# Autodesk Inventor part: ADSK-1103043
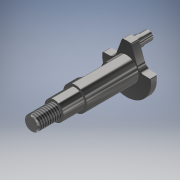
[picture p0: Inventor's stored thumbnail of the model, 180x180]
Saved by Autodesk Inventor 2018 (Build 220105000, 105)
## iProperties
Shininess: 50.0
Length Units: 11272
Angle Units: 11279
Time Units: 11290
Mass Units: 11286
Length Display Precision: 4
Angle Display Precision: 2
Compacted: True
Created: 2000-11
Part Number: ADSK-1103043
Document SubType Name: Modeling
Description: CRANKSHAFT
Mass: 18.2834 g
Surface Area: 21.3592 cm^2
Volume: 2.33206 cm^3
Density: 7.84 g/cm^3
Material: Steel, High Strength Low Alloy
Appearance: Steel - Polished
Density: 0.0
Volumn: 0.0
Area: 0.0
PropertySet Name: Model Information
Control State: 0
Master: False
Checked Out: False
Author: Autodesk, Inc.
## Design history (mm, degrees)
node "Extrusion1" dims "d1" = 30.2625, "d2" = 0
  sketch "Sketch2"
    geometry: C1 r 4.001 at (0, 0); 1 further point
    constraints: 1 centre point, 1 coincident
    dimensions: "d0" = 8.001 diameter of C1
node "Extrusion2" dims "d4" = 3.175, "d5" = 0
  sketch "Sketch3"
    geometry: C1 r 4.001 at (0, 0) reference; C2 r 10.224 at (0, 0)
    constraints: 1 centre point, 1 coincident
    dimensions: "d3" = 20.447 diameter of C2
node "Extrusion6" dims "d23" = 21.5, "d24" = 0
  sketch "Sketch7"
    geometry: C1 r 4.001 at (0, 0) reference; C2 r 5.001 at (0, 0)
    constraints: 1 centre point, 1 coincident
    dimensions: "d22" = 10.00125 diameter of C2
node "Extrusion3" dims "d9" = 3.175, "d10" = 0
  sketch "Sketch4"
    geometry: L1 (-10.144, 1.27)-(-5.15, 1.27); L2 (-5.15, 1.27)-(-1.905, 10.044); L3 (1.905, 10.044)-(5.15, 1.27); L4 (5.15, 1.27)-(10.144, 1.27); C1 r 4.001 at (0, 0) reference; A1 r 10.224 centre (0, 0) between (-10.144, 1.27) and (-1.905, 10.044) reference
    constraints: 8 end point, 4 point on circle, 2 collinear, 2 equal length, 1 horizontal
    dimensions: "d6" = 1.27 distance from line of L4 A1.centre; "d7" = 3.81 distance of L3.start L2.end; "d8" = 1.27 distance edge to line of C1 L2
node "Fillet1" dims "d11" = 0.7874
node "Extrusion4" dims "d13" = 21.336, "d14" = 0
  sketch "Sketch5"
    geometry: C1 r 4.001 at (0, 0) reference; C2 r 3.175 at (0, 0)
    constraints: 1 centre point, 1 coincident
    dimensions: "d12" = 6.35 diameter of C2
node "Chamfer1" dims "d15" = 1.27, "d16" = 5.08, "d44" = 45 deg
node "Fillet2" dims "d17" = 9.525
node "Extrusion5" dims "d20" = 6, "d21" = 0
  sketch "Sketch6"
    geometry: C1 r 1.905 at (0, 7.62); A1 r 10.224 centre (0, 0) between (1.905, 10.044) and (-1.905, 10.044) reference
    constraints: 1 centre point, 1 vertical alignment
    dimensions: "d18" = 3.81 diameter of C1; "d19" = 7.62 distance of A1.centre C1.centre
node "Fillet3" dims "d25" = 3.175
workaxis "Work Axis1"
workaxis "Work Axis2"
workplane "Work Plane1"
node "Revolution1" dims "d28" = 200 deg
  sketch "Sketch8"
    geometry: L1 (10.224, 0)-(10.224, -3.175) reference; L2 (10.224, -3.175)-(-0.523, -3.175) reference; L3 (9.411, -3.175)-(10.224, -2.362); L4 (0, -17.062)-(0, 38.15) reference
    constraints: 2 end point, 2 point on line
    dimensions: "d26" = 0.8128 distance of L1.end L3.end; "d27" = 0.8128 distance from line of L1 L3.start (= d26)
sketch "Sketch9"
  geometry: C1 r 1.905 at (0, 7.62) reference; A1 r 0.787 centre (-1.325, 9.343) between (-1.436, 10.122) and (-2.064, 9.616) reference; 1 further point
  constraints: 1 coincident, 3 other
extrude "Extrusion7" join sketch "Sketch9" distance "d29" = 2.19235; taper "d30" = 0 deg
sketch "Sketch10"
  geometry: C1 r 4.001 at (0, 0) reference; C2 r 3 at (0, 0)
  constraints: 1 centre point, 1 coincident
  dimensions: "d31" = 6 diameter of C2
extrude "Extrusion8" join sketch "Sketch10" distance "d32" = 9.525; taper "d33" = 0 deg
thread "Thread1" dims "d34" = 25.4, "d35" = 0
chamfer "Chamfer2" distance "d36" = 0.381; stored, may be unused: second distance "d37" = 0.381, angle "d45" = 45 deg
sketch "Sketch11"
  geometry: L1 (0, -14.313)-(0, 14.313) reference; L2 (0, 0)-(-4.982, 0.436); C1 r 4.001 at (0, 0) reference
  constraints: 2 end point, 2 other
  dimensions: "d38" = 85 deg angle of L1 L2
workplane "Work Plane2"
sketch "Sketch12"
  geometry: L1 (-5.001, -21.5)-(-5.001, 0) reference; L2 (5.001, -21.5)-(5.001, 0) reference; L3 (-5.001, -4.164)-(5.001, -4.164); L4 (5.001, -4.164)-(5.001, -15.658); L5 (5.001, -15.658)-(-5.001, -15.658); L6 (-5.001, -15.658)-(-5.001, -4.164); L7 (4.001, 0)-(-4.001, 0) reference; L8 (10.224, -21.5)-(0.369, -21.5) reference; 1 further point
  constraints: 8 end point, 2 parallel, 2 point on line, 1 horizontal, 1 perpendicular
  dimensions: "d39" = 4.164 distance between parallel lines of L7 L3; "d40" = 5.842 distance between parallel lines of L8 L5
extrude "Extrusion9" cut sketch "Sketch12" distance "d41" = 3.175; taper "d42" = 0 deg
fillet "Fillet4" dims "d43" = 1.27
body "Solid1"
